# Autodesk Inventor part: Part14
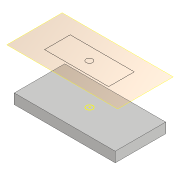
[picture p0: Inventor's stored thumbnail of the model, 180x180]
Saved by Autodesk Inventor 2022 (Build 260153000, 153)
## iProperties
Created: 2015-05
Part Number: Part14
Material: Generic
Document SubType Name: Modeling
Designer: Sandeep
Density: 1 g/cm^3
Appearance: Default
Author: Sandeep
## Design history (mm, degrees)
sketch "Sketch1"
  geometry: L1 (-100, 50)-(100, 50); L2 (100, 50)-(100, -50); L3 (100, -50)-(-100, -50); L4 (-100, -50)-(-100, 50); 1 further point
  constraints: 8 end point, 2 parallel, 1 horizontal, 1 perpendicular
  dimensions: "d0" = 100 distance from line of point (0, 0) L2; "d1" = 200 distance of L1.start L1.end; "d2" = 50 distance from line of point (0, 0) L1; "d3" = 100 distance of L1.end L2.end
extrude "Extrusion1" new body sketch "Sketch1" distance "d4" = 20; taper "d5" = 0 deg
workplane "Work Plane1"
sketch "Sketch2"
  geometry: C1 r 6.35 at (-0.807, -0.346) reference; 1 further point
body "Solid1"
